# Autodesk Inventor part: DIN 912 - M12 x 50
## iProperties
Created: 2006-08
Part Number: DIN 912 - M12 x 50
Material: Stahl, weich, unlegiert
Description: hex socket cap screw
Vendor: Autodesk Inc.
Document SubType Name: Modeling
Standard: DIN 912
Designer: STK
Standards Organization: DIN
Language: de-DE
Size Designation: M12 x 30
Categories: <MemberInstance Version="R10.0.0"><Categories><Category DisplayName="Schrauben" InternalName="e4da775c-781d-43d5-af7c-5136215cf5a6" Mnemonic="FSTN"><Category Di
Density: 7.86 g/cm^3
Author: STK
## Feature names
1. Körper [Revolution]
2. Loch [Extrusion]
3. Rundung1 [Fillet]
4. Fase1 [Chamfer]
